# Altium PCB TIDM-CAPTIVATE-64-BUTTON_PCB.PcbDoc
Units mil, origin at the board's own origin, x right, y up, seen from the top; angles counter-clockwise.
Board outline 4300 x 4800 mil, 2 copper layers (Top Layer, Bottom Layer), stack 62 mil thick; 74 components, 17 nets, 1208 pads, 13 vias.
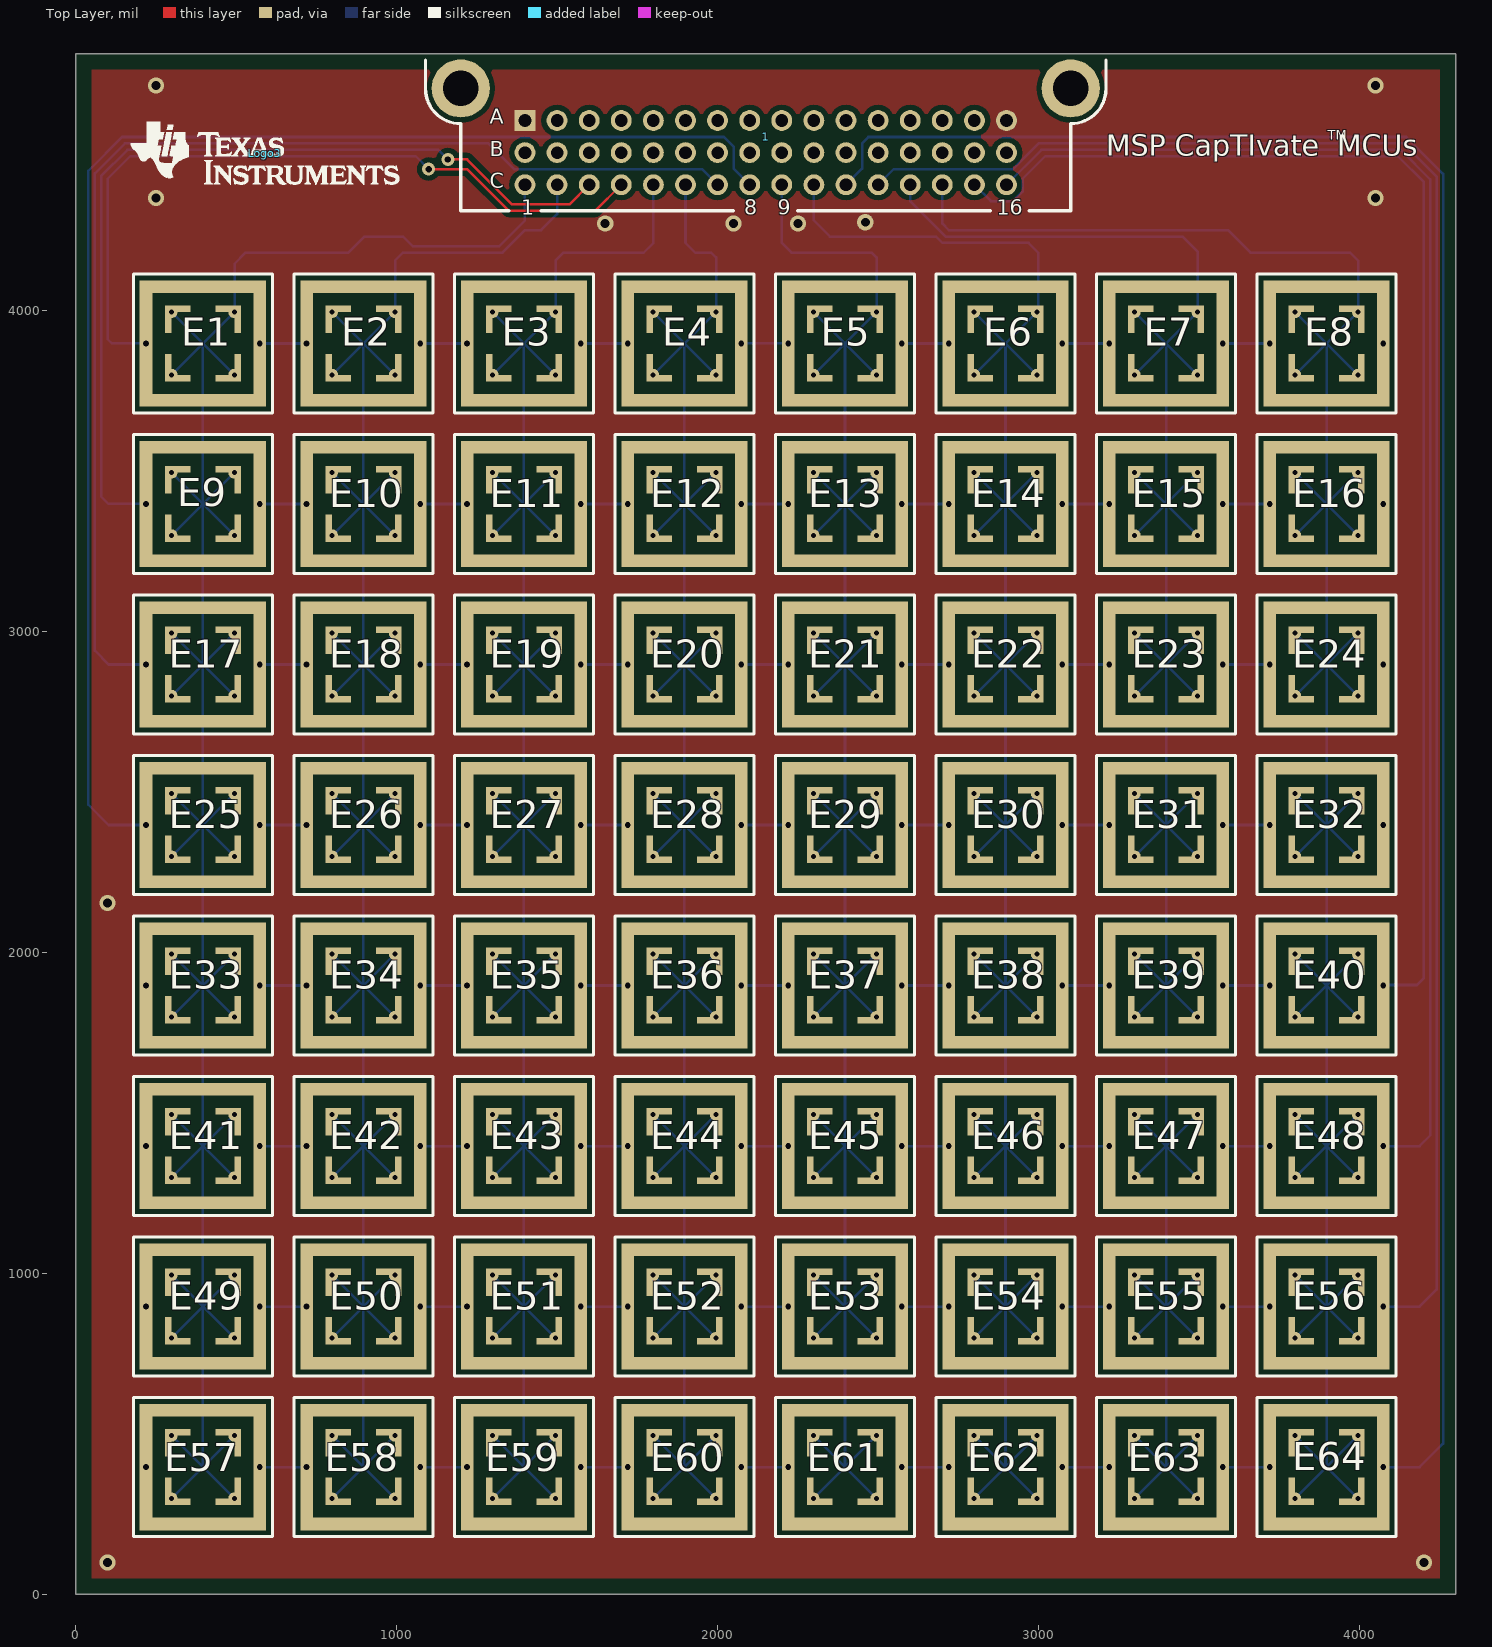
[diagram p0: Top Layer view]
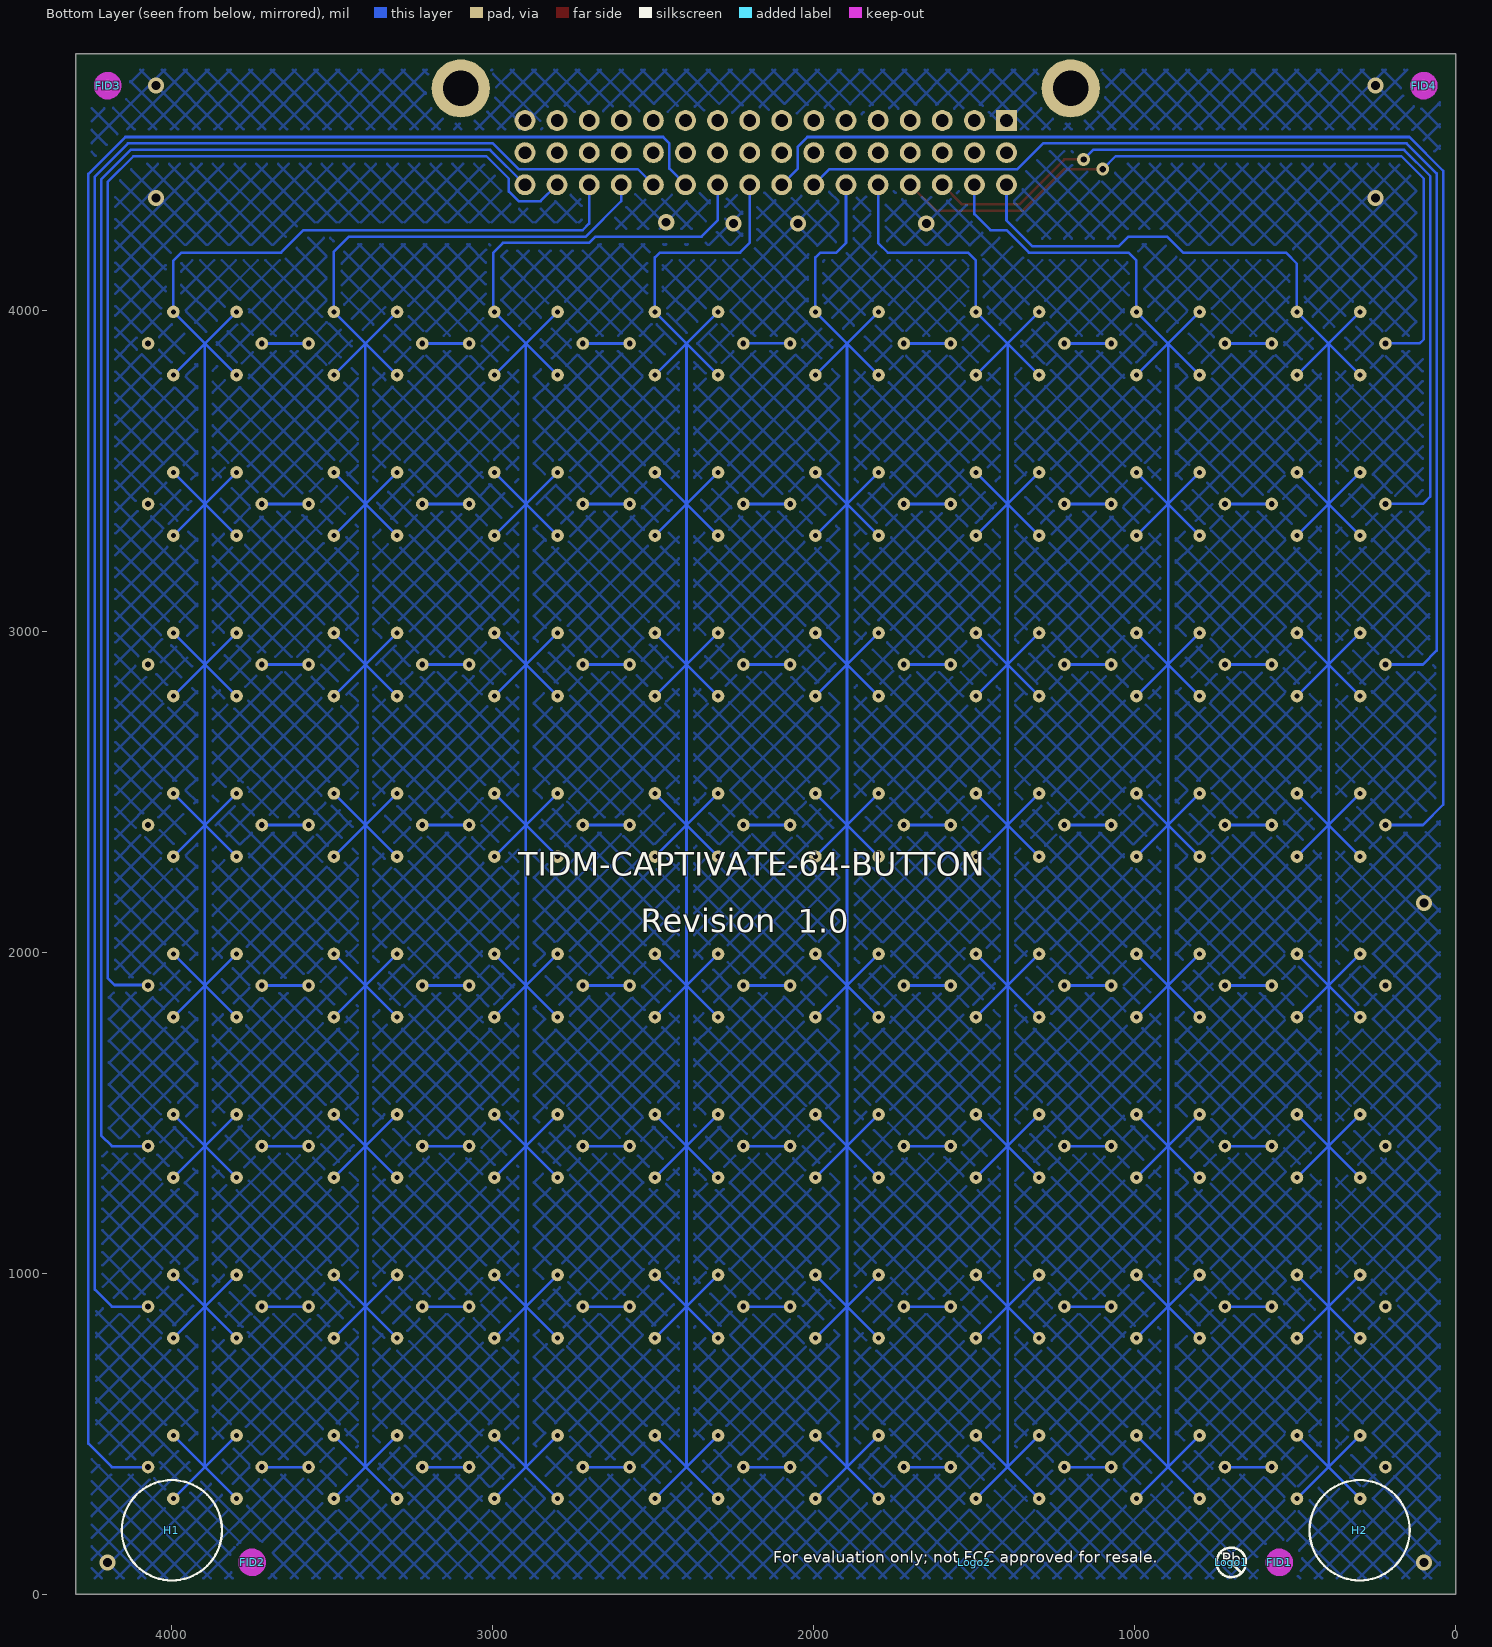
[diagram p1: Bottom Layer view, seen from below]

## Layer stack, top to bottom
Top Solder: solder mask 0.4, Solder Resist, Dk 3.5
Top Layer: signal copper 1.4
Dielectric1: core 59.2, FR-4, Dk 4.8
Bottom Layer: signal copper 1.4
Bottom Solder: solder mask 0.4, Solder Resist, Dk 3.5

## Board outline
0,0 0,4800 4300,4800 4300,0

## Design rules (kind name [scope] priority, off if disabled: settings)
AcuteAngle [All] p1: minimum=3.00000000000000E+0001 checktracksonly=FALSE
AssemblyTestPointUsage [All] p1: valid=2
Clearance Clearance_Keepouts [((IsTrack Or IsArc) And Not InPoly) And IsFree and IsKeepOut vs ((IsTrack Or IsArc) And Not InPoly) And IsFree and IsKeepOut] p1: gap=0
Clearance Clearance_BoardEdge_MountingHoles [OnCopper and InComponentClass('Mounting Holes') vs IsKeepOut] p2: gap=40
Clearance Clearance_BoardEdge_Poly [OnCopper and InPoly vs IsKeepOut] p3: gap=25
Clearance Clearance_BoardEdge [OnCopper and Not InComponentClass('Logo') and not InComponentClass('FiducialMark') and not InRegion(1000,500,4000,800) and Not IsKeepout vs IsKeepOut] p4: gap=75
Clearance Clearance_Poly [InPolygon] p5: gap=16
Clearance [All] p6: gap=6
ComponentClearance ComponentClearance_MountingHoles_FiducialMarks [InComponentClass('Mounting Holes') vs InComponentClass('FiducialMark')] p1: gap=50 collisioncheckmode=3 verticalgap=10 showdistances=FALSE
ComponentClearance ComponentClearance_Shunt [InComponentClass('Header') vs InComponentClass('Shunt')] p2: gap=0 collisioncheckmode=3 verticalgap=0 showdistances=FALSE
ComponentClearance ComponentClearance_Logo [InComponentClass('Logo')] p3: gap=50 collisioncheckmode=3 verticalgap=10 showdistances=FALSE
ComponentClearance ComponentClearance_ScrewToNut [(HasFootprint('NY PMS 440 0025 PH')) vs (HasFootprint('Keystone_1902C'))] p4: gap=5 collisioncheckmode=3 verticalgap=10 showdistances=FALSE
ComponentClearance ComponentClearance_MountingHoles [InComponentClass('Mounting Holes')] p5: gap=250 collisioncheckmode=3 verticalgap=100000 showdistances=FALSE
ComponentClearance ComponentClearance_SmallPassives [HasFootprint('0201*') or HasFootprint('0402*') or HasFootprint('0508') or HasFootprint('0603*') or HasFootprint('0612') or HasFootprint('0805*') or HasFootprint('0815*') or HasFootprint('0830*') or HasFootprint('1206*') or HasFootprint('1210*') or HasFootprint('1808*') or HasFootprint('1812*') or HasFootprint('1825*') or HasFootprint('2010*') or HasFootprint('2220*') or HasFootprint('2225*') or HasFootprint('2512*') or HasFootprint('2728*') or HasFootprint('3518*') vs HasFootprint('0201*') or HasFootprint('0402*') or HasFootprint('0508') or HasFootprint('0603*') or HasFootprint('0612') or HasFootprint('0805*') or HasFootprint('0815*') or HasFootprint('0830*') or HasFootprint('1206*') or HasFootprint('1210*') or HasFootprint('1808*') or HasFootprint('1812*') or HasFootprint('1825*') or HasFootprint('2010*') or HasFootprint('2220*') or HasFootprint('2225*') or HasFootprint('2512*') or HasFootprint('2728*') or HasFootprint('3518*')] p6: gap=20 collisioncheckmode=3 verticalgap=10 showdistances=FALSE
ComponentClearance ComponentClearance_THtoSMT [IsThruComponent vs IsSMTComponent] p7: gap=100 collisioncheckmode=3 verticalgap=30 showdistances=FALSE
ComponentClearance ComponentClearance_THtoTH [IsThruComponent vs IsThruComponent] p8: gap=50 collisioncheckmode=3 verticalgap=30 showdistances=FALSE
ComponentClearance [All] p9: gap=30 collisioncheckmode=3 verticalgap=10 showdistances=FALSE
DiffPairsRouting [All] p1: maxlimit=100 minlimit=10 mostfreqgap=10 toplayer_minwidth=15 toplayer_maxwidth=15 toplayer_prefwidth=15 bottomlayer_minwidth=15 bottomlayer_maxwidth=15 bottomlayer_prefwidth=15 maxuncoupledlength=1000
FabricationTestPointUsage TestPointUsage [All] p1: valid=2 allowmultiple=FALSE
FabricationTestpoint Testpoint [All] p1: side=3 testpointundercomponent=TRUE minsize=40 maxsize=100 preferedsize=60 minholesize=0 maxholesize=40 preferedholesize=32 testpointgrid=1 allowsidetop=TRUE allowsidebottom=TRUE usegrid=TRUE gridtolerance=0.01
FanoutControl Fanout_LCC [IsLCC] p1: bgadir=Out bgaviamode=Centered fanoutstyle=Auto fanoutdirection=Alternating viagrid=1 // Fanout_LCC (Default Rule)
FanoutControl Fanout_BGA [IsBGA] p2: bgadir=Out bgaviamode=Centered fanoutstyle=Auto fanoutdirection=Alternating viagrid=1 // Fanout_BGA (Default Rule)
FanoutControl Fanout_Default [All] p4: bgadir=Out bgaviamode=Centered fanoutstyle=Auto fanoutdirection=Alternating viagrid=1 // Fanout_Default (Default Rule)
FanoutControl Fanout_Small [(CompPinCount < 5)] p5: bgadir=Out bgaviamode=Centered fanoutstyle=Auto fanoutdirection=OutThenIn viagrid=1 // Fanout_Small (Default Rule)
HoleSize [All] p1: absolutevalues=TRUE maxlimit=251 minlimit=8 maxpercent=80.000 minpercent=20.000
MinimumAnnularRing MinimumAnnularRing_ThermalPadVias [IsVia and InAnyComponent] p1: minimumring=5.91
MinimumAnnularRing [All] p2: minimumring=9
MinimumSolderMaskSliver MinimumSolderMaskSliver_Logo [InComponentClass('Logo') vs InComponentClass('Logo')] p1: minsoldermaskwidth=0.7
MinimumSolderMaskSliver [All] p2: minsoldermaskwidth=3.94
PlaneConnect [All] p1: planeconnectstyle=Direct reliefexpansion=10 reliefentries=4 reliefconductorwidth=10 reliefairgap=10
PolygonConnect [All] p1: connectstyle=Direct reliefconductorwidth=10 reliefentries=4 polygonreliefangle="90 Angle" airgapwidth=10
RoutingVias ThermalPadVias [IsVia and InAnyComponent] p1: holewidth=7.87 width=19.68 viastyle="Through Hole" minholewidth=7.87 minwidth=19.68 maxholewidth=12.99 maxwidth=23.62
RoutingVias [All] p2: holewidth=16 width=34 viastyle="Through Hole" minholewidth=7.87 minwidth=26 maxholewidth=40 maxwidth=65
SilkToBoardRegionClearance [Not ((IsComment or IsDesignator) And (Hide <> 'False')) and not InRegion(1000,500,4000,800)] p1:
SilkToSilkClearance SilkToSilkClearance_Pb-FreeLogo [(HasFootprint('Pb-Free_Overlay_Medium') OR HasFootprint('Pb-Free_Overlay_Small')) vs (HasFootprint('Pb-Free_Overlay_Medium') OR HasFootprint('Pb-Free_Overlay_Small'))] p1: silktosilkclearance=0
SilkToSilkClearance [All] p2: silktosilkclearance=5
SilkToSolderMaskClearance "Silk to Solder Mask Opening" [All] p1: minsilkscreentomaskgap=1 clearancetoexposedcopper=FALSE
SolderMaskExpansion [All] p1: expansion=3
UnpouredPolygon [All] p1: allowunpoured=FALSE
Width [All] p1: maxlimit=100 minlimit=6 preferedwidth=10 checkconnectedcopper=TRUE
14 further rules are at their usual default settings.

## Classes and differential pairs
component class Logo: Logo3
component class FiducialMark: FID1 FID2 FID3 FID4
component class TIDM-CAPTIVATE-64-BUTTON_Hardware: FID1 FID2 FID3 FID4 H1 H2 Logo1 Logo2 Logo3 Logo4
component class TIDM-CAPTIVATE-64-BUTTON_Circuit: 1 E1 E2 E3 E4 E5 E6 E7 E8 E9 E10 E11 E12 E13 E14 E15 E16 E17 E18 E19 E20 E21 E22 E23 E24 E25 E26 E27 E28 E29 E30 E31 E32 E33 E34 E35 E36 E37 E38 E39 E40 E41 E42 E43 E44 E45 E46 E47 E48 E49 E50 E51 E52 E53 E54 E55 E56 E57 E58 E59 E60 E61 E62 E63 E64

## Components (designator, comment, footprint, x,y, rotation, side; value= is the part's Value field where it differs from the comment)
1 "CAPTIVATE-CONN-FR2633-PANEL" CAPTIVATE-CONN-48 2150,4800 r0 top
E1 "Btn-Mutual_HighSens" electrode-mutual-highsensitivity-cut-rotated#1 200,3700 r0 top
E2 "Btn-Mutual_HighSens" electrode-mutual-highsensitivity-cut-rotated#1 700,3700 r0 top
E3 "Btn-Mutual_HighSens" electrode-mutual-highsensitivity-cut-rotated#1 1200,3700 r0 top
E4 "Btn-Mutual_HighSens" electrode-mutual-highsensitivity-cut-rotated#1 1700,3700 r0 top
E5 "Btn-Mutual_HighSens" electrode-mutual-highsensitivity-cut-rotated#1 2200,3700 r0 top
E6 "Btn-Mutual_HighSens" electrode-mutual-highsensitivity-cut-rotated#2 2700,3700 r0 top
E7 "Btn-Mutual_HighSens" electrode-mutual-highsensitivity-cut-rotated#1 3200,3700 r0 top
E8 "Btn-Mutual_HighSens" electrode-mutual-highsensitivity-cut-rotated#1 3700,3700 r0 top
E9 "Btn-Mutual_HighSens" electrode-mutual-highsensitivity-cut-rotated#2 200,3200 r0 top
E10 "Btn-Mutual_HighSens" electrode-mutual-highsensitivity-cut-rotated#2 700,3200 r0 top
E11 "Btn-Mutual_HighSens" electrode-mutual-highsensitivity-cut-rotated#2 1200,3200 r0 top
E12 "Btn-Mutual_HighSens" electrode-mutual-highsensitivity-cut-rotated#2 1700,3200 r0 top
E13 "Btn-Mutual_HighSens" electrode-mutual-highsensitivity-cut-rotated#2 2200,3200 r0 top
E14 "Btn-Mutual_HighSens" electrode-mutual-highsensitivity-cut-rotated#2 2700,3200 r0 top
E15 "Btn-Mutual_HighSens" electrode-mutual-highsensitivity-cut-rotated#2 3200,3200 r0 top
E16 "Btn-Mutual_HighSens" electrode-mutual-highsensitivity-cut-rotated#2 3700,3200 r0 top
E17 "Btn-Mutual_HighSens" electrode-mutual-highsensitivity-cut-rotated#2 200,2700 r0 top
E18 "Btn-Mutual_HighSens" electrode-mutual-highsensitivity-cut-rotated#2 700,2700 r0 top
E19 "Btn-Mutual_HighSens" electrode-mutual-highsensitivity-cut-rotated#2 1200,2700 r0 top
E20 "Btn-Mutual_HighSens" electrode-mutual-highsensitivity-cut-rotated#2 1700,2700 r0 top
E21 "Btn-Mutual_HighSens" electrode-mutual-highsensitivity-cut-rotated#2 2200,2700 r0 top
E22 "Btn-Mutual_HighSens" electrode-mutual-highsensitivity-cut-rotated#2 2700,2700 r0 top
E23 "Btn-Mutual_HighSens" electrode-mutual-highsensitivity-cut-rotated#2 3200,2700 r0 top
E24 "Btn-Mutual_HighSens" electrode-mutual-highsensitivity-cut-rotated#2 3700,2700 r0 top
E25 "Btn-Mutual_HighSens" electrode-mutual-highsensitivity-cut-rotated#2 200,2200 r0 top
E26 "Btn-Mutual_HighSens" electrode-mutual-highsensitivity-cut-rotated#2 700,2200 r0 top
E27 "Btn-Mutual_HighSens" electrode-mutual-highsensitivity-cut-rotated#2 1200,2200 r0 top
E28 "Btn-Mutual_HighSens" electrode-mutual-highsensitivity-cut-rotated#2 1700,2200 r0 top
E29 "Btn-Mutual_HighSens" electrode-mutual-highsensitivity-cut-rotated#2 2200,2200 r0 top
E30 "Btn-Mutual_HighSens" electrode-mutual-highsensitivity-cut-rotated#2 2700,2200 r0 top
E31 "Btn-Mutual_HighSens" electrode-mutual-highsensitivity-cut-rotated#2 3200,2200 r0 top
E32 "Btn-Mutual_HighSens" electrode-mutual-highsensitivity-cut-rotated#2 3700,2200 r0 top
E33 "Btn-Mutual_HighSens" electrode-mutual-highsensitivity-cut-rotated#2 200,1700 r0 top
E34 "Btn-Mutual_HighSens" electrode-mutual-highsensitivity-cut-rotated#2 700,1700 r0 top
E35 "Btn-Mutual_HighSens" electrode-mutual-highsensitivity-cut-rotated#2 1200,1700 r0 top
E36 "Btn-Mutual_HighSens" electrode-mutual-highsensitivity-cut-rotated#2 1700,1700 r0 top
E37 "Btn-Mutual_HighSens" electrode-mutual-highsensitivity-cut-rotated#2 2200,1700 r0 top
E38 "Btn-Mutual_HighSens" electrode-mutual-highsensitivity-cut-rotated#2 2700,1700 r0 top
E39 "Btn-Mutual_HighSens" electrode-mutual-highsensitivity-cut-rotated#2 3200,1700 r0 top
E40 "Btn-Mutual_HighSens" electrode-mutual-highsensitivity-cut-rotated#2 3700,1700 r0 top
E41 "Btn-Mutual_HighSens" electrode-mutual-highsensitivity-cut-rotated#2 200,1200 r0 top
E42 "Btn-Mutual_HighSens" electrode-mutual-highsensitivity-cut-rotated#2 700,1200 r0 top
E43 "Btn-Mutual_HighSens" electrode-mutual-highsensitivity-cut-rotated#2 1200,1200 r0 top
E44 "Btn-Mutual_HighSens" electrode-mutual-highsensitivity-cut-rotated#2 1700,1200 r0 top
E45 "Btn-Mutual_HighSens" electrode-mutual-highsensitivity-cut-rotated#2 2200,1200 r0 top
E46 "Btn-Mutual_HighSens" electrode-mutual-highsensitivity-cut-rotated#2 2700,1200 r0 top
E47 "Btn-Mutual_HighSens" electrode-mutual-highsensitivity-cut-rotated#2 3200,1200 r0 top
E48 "Btn-Mutual_HighSens" electrode-mutual-highsensitivity-cut-rotated#2 3700,1200 r0 top
E49 "Btn-Mutual_HighSens" electrode-mutual-highsensitivity-cut-rotated#2 200,700 r0 top
E50 "Btn-Mutual_HighSens" electrode-mutual-highsensitivity-cut-rotated#2 700,700 r0 top
E51 "Btn-Mutual_HighSens" electrode-mutual-highsensitivity-cut-rotated#2 1200,700 r0 top
E52 "Btn-Mutual_HighSens" electrode-mutual-highsensitivity-cut-rotated#2 1700,700 r0 top
E53 "Btn-Mutual_HighSens" electrode-mutual-highsensitivity-cut-rotated#2 2200,700 r0 top
E54 "Btn-Mutual_HighSens" electrode-mutual-highsensitivity-cut-rotated#2 2700,700 r0 top
E55 "Btn-Mutual_HighSens" electrode-mutual-highsensitivity-cut-rotated#2 3200,700 r0 top
E56 "Btn-Mutual_HighSens" electrode-mutual-highsensitivity-cut-rotated#2 3700,700 r0 top
E57 "Btn-Mutual_HighSens" electrode-mutual-highsensitivity-cut-rotated#2 200,200 r0 top
E58 "Btn-Mutual_HighSens" electrode-mutual-highsensitivity-cut-rotated#2 700,200 r0 top
E59 "Btn-Mutual_HighSens" electrode-mutual-highsensitivity-cut-rotated#2 1200,200 r0 top
E60 "Btn-Mutual_HighSens" electrode-mutual-highsensitivity-cut-rotated#2 1700,200 r0 top
E61 "Btn-Mutual_HighSens" electrode-mutual-highsensitivity-cut-rotated#2 2200,200 r0 top
E62 "Btn-Mutual_HighSens" electrode-mutual-highsensitivity-cut-rotated#2 2700,200 r0 top
E63 "Btn-Mutual_HighSens" electrode-mutual-highsensitivity-cut-rotated#2 3200,200 r0 top
E64 "Btn-Mutual_HighSens" electrode-mutual-highsensitivity-cut-rotated#2 3700,200 r0 top
FID1 "Fiducial" Fiducial10-20 550,100 r180 bottom
FID2 "Fiducial" Fiducial10-20 3750,100 r180 bottom
FID3 "Fiducial" Fiducial10-20 4200,4700 r180 bottom
FID4 "Fiducial" Fiducial10-20 100,4700 r180 bottom
H1 "SJ61A1" Bumpon_SJ61A1 4000,200 r180 bottom
H2 "SJ61A1" Bumpon_SJ61A1 300,200 r180 bottom
Logo1 "Pb-Free Symbol" Pb-Free_Overlay_Small 700,100 r180 bottom
Logo2 "FCC disclaimer" FCC_disclaimer 1500,100 r180 bottom
Logo3 "Texas Instruments" TI_Stacked_Overlay_Small 590,4490 r0 top

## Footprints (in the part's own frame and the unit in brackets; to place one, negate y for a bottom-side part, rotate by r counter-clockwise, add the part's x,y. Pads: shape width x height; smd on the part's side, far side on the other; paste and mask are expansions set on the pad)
Bumpon_SJ61A1 [mil] "3M Cylindrical Bumpon black"
  round 1 on Mech4: 0(0,0)
  silkscreen extent -156,-156 156,156, body extent -156,-155 156,156, height 201
CAPTIVATE-CONN-48 [mm] "Connector, 3x16, 100mil, TH, RA"
  rect 1.65x1.65 hole 1: A1(-19.05,-5.3)
  round 1.65 hole 1: A2(-16.51,-5.3) A3(-13.97,-5.3) A4(-11.43,-5.3) A5(-8.89,-5.3) A6(-6.35,-5.3) A7(-3.81,-5.3) A8(-1.27,-5.3) A9(1.27,-5.3) A10(3.81,-5.3) A11(6.35,-5.3) A12(8.89,-5.3) A13(11.43,-5.3) A14(13.97,-5.3) A15(16.51,-5.3) A16(19.05,-5.3) B1(-19.05,-7.84) B2(-16.51,-7.84) B3(-13.97,-7.84) B4(-11.43,-7.84) B5(-8.89,-7.84) B6(-6.35,-7.84) B7(-3.81,-7.84) B8(-1.27,-7.84) B9(1.27,-7.84) B10(3.81,-7.84) B11(6.35,-7.84) B12(8.89,-7.84) B13(11.43,-7.84) B14(13.97,-7.84) B15(16.51,-7.84) B16(19.05,-7.84) C1(-19.05,-10.38) C2(-16.51,-10.38) C3(-13.97,-10.38) C4(-11.43,-10.38) C5(-8.89,-10.38) C6(-6.35,-10.38) C7(-3.81,-10.38) C8(-1.27,-10.38) C9(1.27,-10.38) C10(3.81,-10.38) C11(6.35,-10.38) C12(8.89,-10.38) C13(11.43,-10.38) C14(13.97,-10.38) C15(16.51,-10.38) C16(19.05,-10.38)
  round 4.6 hole 2.8: H1(-24.13,-2.76) H2(24.13,-2.76)
  silkscreen extent -26.92,-12.45 26.92,-0.51, body extent -27.05,-5.46 27.05,6.98, height 6.6
electrode-mutual-highsensitivity-cut-rotated#1 [mm] "Mutual Capacitance Sensing Electrode with High Sensitivity and Cut Rx Square (Rotated)"
  rect 0.5x1.667 smd paste+0: RX(2.25,3.333) RX(2.25,6.667) RX(7.75,3.333) RX(7.75,6.667)
  round 1 hole 0.4: RX(2.5,2.5) RX(2.5,7.5) RX(7.5,2.5) RX(7.5,7.5)
  rect 2x0.5 smd paste+0: RX(3,2.25) RX(3,7.75) RX(7,2.25) RX(7,7.75)
  rect 1x10 smd paste+0: TX(0.5,5) TX(9.5,5)
  round 1 hole 0.45: TX(0.5,5) TX(9.5,5)
  rect 10x1 smd paste+0: TX(5,0.5) TX(5,9.5)
  Bottom Layer lines w0.2: 2.5,2.5 5,5 ; 2.5,7.5 5,5 ; 7.5,2.5 5,5 ; 7.5,7.5 5,5
  silkscreen extent -0.5,-0.5 10.5,10.5
electrode-mutual-highsensitivity-cut-rotated#2 [mm] "Mutual Capacitance Sensing Electrode with High Sensitivity and Cut Rx Square (Rotated)"
  rect 0.5x1.667 smd paste+0: RX(2.25,3.333) RX(2.25,6.667) RX(7.75,3.333) RX(7.75,6.667)
  round 1 hole 0.4: RX(2.5,2.5) RX(2.5,7.5) RX(7.5,2.5) RX(7.5,7.5)
  rect 2x0.5 smd paste+0: RX(3,2.25) RX(3,7.75) RX(7,2.25) RX(7,7.75)
  rect 1x10 smd paste+0: TX(0.5,5) TX(9.5,5)
  round 1 hole 0.45: TX(0.5,5) TX(9.5,5)
  rect 10x1 smd paste+0: TX(5,0.5) TX(5,9.5)
  Bottom Layer lines w0.2: 2.5,2.5 7.5,7.5 ; 2.5,7.5 7.5,2.5
  silkscreen extent -0.5,-0.5 10.5,10.5
FCC_disclaimer [mil]
Fiducial10-20 [mm]
  round 1 smd mask+0.5: 1(0,0)
  Top Layer keep-out circle w1.178: c0,0 r0.5
Pb-Free_Overlay_Small [mil]
  silkscreen extent -46,-46 46,46
TI_Stacked_Overlay_Small [mil]
  silkscreen extent -418,-98 418,98

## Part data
1: library part CAPTIVATE-CONN-MSP-EXP430FR2633-PANEL, "CapTIvate Panel-Side Connector, 3x16, 100mil, TH, RA, M, MSP-EXP430FR2633"
E1 E2 E3 E4 E5 E6 E7 E8 E9 E10 E11 E12 E13 E14 E15 E16 E17 E18 E19 E20 E21 E22 E23 E24 E25 E26 E27 E28 E29 E30 E31 E32 E33 E34 E35 E36 E37 E38 E39 E40 E41 E42 E43 E44 E45 E46 E47 E48 E49 E50 E51 E52 E53 E54 E55 E56 E57 E58 E59 E60 E61 E62 E63 E64: library part btn-mutual-highsens, "Capacitive Button, Mutual, 2-layer, 10mm, High Sensitivity"
FID1 FID2 FID3 FID4: "Fiducial mark.  There is nothing to buy or mount."
H1 H2: "Bumpon, Cylindrical, 0.312 X 0.200, Black"
Logo1: library part Pb-Free
Logo2: library part FCC_disclaimer, "FCC_disclaimer"
Logo3: library part TI_Logo, "Texas Instrument Corporate Signature"

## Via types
v1: diameter 50, hole 28, Top Layer to Bottom Layer, 11 vias
v2: diameter 40, hole 20, Top Layer to Bottom Layer, 2 vias

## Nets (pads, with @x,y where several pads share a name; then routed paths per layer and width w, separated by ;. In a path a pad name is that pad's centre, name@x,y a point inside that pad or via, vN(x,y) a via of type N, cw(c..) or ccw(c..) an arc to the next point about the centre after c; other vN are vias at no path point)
GND: 1.A1 1.A16
  other v1: 100,100 4200.18,99.82 100,2154.23 1650,4269.87 2050,4270 2250,4270 2460,4274.46 250,4350 4050,4350 250,4700 4050,4700
RX0: 1.C1 E1.RX E9.RX E17.RX E25.RX E33.RX E41.RX E49.RX E57.RX | length 4746.7
  Bottom Layer w7.87: 396.85,396.85 396.85,3896.85 ; E1.RX@495.28,3995.28 495.28,4145.28 530,4180 850,4180 900,4230 1020,4230 1050,4200 1320,4200 1400,4280 1.C1
RX1: 1.C2 E2.RX E10.RX E18.RX E26.RX E34.RX E42.RX E50.RX E58.RX | length 4316
  Bottom Layer w7.87: 896.85,396.85 896.85,3896.85 ; E2.RX@995.28,3995.28 995.28,4155.28 1020,4180 1330,4180 1400,4250 1450,4250 1500,4300 1.C2
RX2: 1.C5 E3.RX E11.RX E19.RX E27.RX E35.RX E43.RX E51.RX E59.RX | length 4168.7
  Bottom Layer w7.87: 1396.85,396.85 1396.85,3896.85 ; E3.RX@1495.28,3995.28 1495.28,4155.28 1520,4180 1770,4180 1800,4210 1.C5
RX3: 1.C6 E4.RX E12.RX E20.RX E28.RX E36.RX E44.RX E52.RX E60.RX | length 3964.8
  Bottom Layer w7.87: 1896.85,396.85 1896.85,3896.85 ; 1.C6 1900,4210 1930,4180 1980,4180 1995.28,4164.72 E4.RX@1995.28,3995.28
RX4: 1.C9 E5.RX E13.RX E21.RX E29.RX E37.RX E45.RX E53.RX E61.RX | length 4164.8
  Bottom Layer w7.87: 1.C9 2200,4210 2230,4180 2480,4180 2495.28,4164.72 E5.RX@2495.28,3995.28 ; 2396.85,396.85 2396.85,3896.85
RX5: 1.C10 E6.RX E14.RX E22.RX E30.RX E38.RX E46.RX E54.RX E62.RX | length 4532.8
  Bottom Layer w7.87: 1.C10 2300,4280 2350,4230 2680,4230 2700,4210 2968.5,4210 2998.5,4180 E6.RX@2998.5,3998.5 ; 2896.85,396.85 2896.85,3896.85
RX6: 1.C13 E7.RX E15.RX E23.RX E31.RX E39.RX E47.RX E55.RX E63.RX | length 4699.5
  Bottom Layer w7.87: 1.C13 2600,4340 2710,4230 3448.5,4230 3495.28,4183.23 E7.RX@3495.28,3995.28 ; 3396.85,396.85 3396.85,3896.85
RX7: 1.C14 E8.RX E16.RX E24.RX E32.RX E40.RX E48.RX E56.RX E64.RX | length 5123.8
  Bottom Layer w7.87: 1.C14 2700,4270 2720,4250 3590,4250 3660,4180 3970,4180 3995.28,4154.72 E8.RX@3995.28,3995.28 ; 3896.85,396.85 3896.85,3896.85
TX0: 1.C4 E1.TX E2.TX E3.TX E4.TX E5.TX E6.TX E7.TX E8.TX | length 3377.9
  Top Layer w7.87: v2(1100,4440) 1220,4440 1350,4310 1618.66,4310 1.C4
  Bottom Layer w7.87: E1.TX@219.68,3896.85 113.15,3896.85 100,3910 100,4410 170,4480 1060,4480 v2(1100,4440) ; E4.TX@2074.02,3896.85 E5.TX@2219.68,3896.85
  Bottom Layer w8: E1.TX@574.02,3896.85 E2.TX@719.68,3896.85 ; E2.TX@1074.02,3896.85 E3.TX@1219.68,3896.85 ; E3.TX@1574.02,3896.85 E4.TX@1719.68,3896.85 ; E5.TX@2574.02,3896.85 E6.TX@2719.68,3896.85 ; E6.TX@3074.02,3896.85 E7.TX@3219.68,3896.85 ; E7.TX@3574.02,3896.85 E8.TX@3719.69,3896.85
TX1: 1.C3 E9.TX E10.TX E11.TX E12.TX E13.TX E14.TX E15.TX E16.TX | length 3816.9
  Top Layer w7.87: v2(1160,4470) 1220,4470 1360,4330 1538.66,4330 1.C3
  Bottom Layer w7.87: E9.TX@219.68,3396.85 103.15,3396.85 80,3420 80,4418.28 161.72,4500 1130,4500 v2(1160,4470)
  Bottom Layer w8: E9.TX@574.02,3396.85 E10.TX@719.68,3396.85 ; E10.TX@1074.02,3396.85 E11.TX@1219.68,3396.85 ; E11.TX@1574.02,3396.85 E12.TX@1719.68,3396.85 ; E12.TX@2074.02,3396.85 E13.TX@2219.68,3396.85 ; E13.TX@2574.02,3396.85 E14.TX@2719.68,3396.85 ; E14.TX@3074.02,3396.85 E15.TX@3219.68,3396.85 ; E15.TX@3574.02,3396.85 E16.TX@3719.69,3396.85
TX2: 1.C7 E17.TX E18.TX E19.TX E20.TX E21.TX E22.TX E23.TX E24.TX | length 4715.8
  Bottom Layer w7.87: E17.TX@219.68,2896.85 103.15,2896.85 60,2940 60,4426.57 153.43,4520 1286.21,4520 1366.21,4440 1951.34,4440 1.C7
  Bottom Layer w8: E17.TX@574.02,2896.85 E18.TX@719.68,2896.85 ; E18.TX@1074.02,2896.85 E19.TX@1219.68,2896.85 ; E19.TX@1574.02,2896.85 E20.TX@1719.68,2896.85 ; E20.TX@2074.02,2896.85 E21.TX@2219.68,2896.85 ; E21.TX@2574.02,2896.85 E22.TX@2719.68,2896.85 ; E22.TX@3074.02,2896.85 E23.TX@3219.68,2896.85 ; E23.TX@3574.02,2896.85 E24.TX@3719.69,2896.85
TX3: 1.C8 E25.TX E26.TX E27.TX E28.TX E29.TX E30.TX E31.TX E32.TX | length 5405.7
  Bottom Layer w7.87: E25.TX@219.68,2396.85 103.15,2396.85 40,2460 40,4434.85 145.15,4540 2020,4540 2050,4510 2050,4441.34 1.C8 ; E29.TX@2574.02,2396.85 E30.TX@2719.68,2396.85
  Bottom Layer w8: E25.TX@574.02,2396.85 E26.TX@719.68,2396.85 ; E26.TX@1074.02,2396.85 E27.TX@1219.68,2396.85 ; E27.TX@1574.02,2396.85 E28.TX@1719.68,2396.85 ; E28.TX@2074.02,2396.85 E29.TX@2219.68,2396.85 ; E30.TX@3074.02,2396.85 E31.TX@3219.68,2396.85 ; E31.TX@3574.02,2396.85 E32.TX@3719.69,2396.85
TX4: 1.C15 E33.TX E34.TX E35.TX E36.TX E37.TX E38.TX E39.TX E40.TX | length 5168.7
  Bottom Layer w7.87: 1.C15 2851.34,4340 2920,4340 2950,4370 2950,4410 3020,4480 4120,4480 4200,4400 4200,1920 4178.5,1898.5 4140,1898.5 E40.TX@4075.67,1898.5
  Bottom Layer w8: E33.TX@574.02,1896.85 E34.TX@719.68,1896.85 ; E34.TX@1074.02,1896.85 E35.TX@1219.68,1896.85 ; E35.TX@1574.02,1896.85 E36.TX@1719.68,1896.85 ; E36.TX@2074.02,1896.85 E37.TX@2219.68,1896.85 ; E37.TX@2574.02,1896.85 E38.TX@2719.68,1896.85 ; E38.TX@3074.02,1896.85 E39.TX@3219.68,1896.85 ; E39.TX@3574.02,1896.85 E40.TX@3719.69,1896.85
TX5: 1.C16 E41.TX E42.TX E43.TX E44.TX E45.TX E46.TX E47.TX E48.TX | length 5560.7
  Bottom Layer w7.87: 1.C16 3008.66,4500 4128.28,4500 4220,4408.28 4220,1430 4186.85,1396.85 E48.TX@4074.02,1396.85
  Bottom Layer w8: E41.TX@574.02,1396.85 E42.TX@719.68,1396.85 ; E42.TX@1074.02,1396.85 E43.TX@1219.68,1396.85 ; E43.TX@1574.02,1396.85 E44.TX@1719.68,1396.85 ; E44.TX@2074.02,1396.85 E45.TX@2219.68,1396.85 ; E45.TX@2574.02,1396.85 E46.TX@2719.68,1396.85 ; E46.TX@3074.02,1396.85 E47.TX@3219.68,1396.85 ; E47.TX@3574.02,1396.85 E48.TX@3719.69,1396.85
TX6: 1.C12 E49.TX E50.TX E51.TX E52.TX E53.TX E54.TX E55.TX E56.TX | length 6510.4
  Bottom Layer w7.87: 1.C12 2548.66,4440 2920,4440 3000,4520 4136.57,4520 4240,4416.57 4240,950 4186.85,896.85 E56.TX@4074.02,896.85
  Bottom Layer w8: E49.TX@574.02,896.85 E50.TX@719.68,896.85 ; E50.TX@1074.02,896.85 E51.TX@1219.68,896.85 ; E51.TX@1574.02,896.85 E52.TX@1719.68,896.85 ; E52.TX@2074.02,896.85 E53.TX@2219.68,896.85 ; E53.TX@2574.02,896.85 E54.TX@2719.68,896.85 ; E54.TX@3074.02,896.85 E55.TX@3219.68,896.85 ; E55.TX@3574.02,896.85 E56.TX@3719.69,896.85
TX7: 1.C11 E57.TX E58.TX E59.TX E60.TX E61.TX E62.TX E63.TX E64.TX | length 7206.2
  Bottom Layer w7.87: 1.C11 2450,4441.34 2450,4520 2470,4540 4144.85,4540 4260,4424.85 4260,470 4186.85,396.85 E64.TX@4074.02,396.85
  Bottom Layer w8: E57.TX@574.02,396.85 E58.TX@719.68,396.85 ; E58.TX@1074.02,396.85 E59.TX@1219.68,396.85 ; E59.TX@1574.02,396.85 E60.TX@1719.68,396.85 ; E60.TX@2074.02,396.85 E61.TX@2219.68,396.85 ; E61.TX@2574.02,396.85 E62.TX@2719.68,396.85 ; E62.TX@3074.02,396.85 E63.TX@3219.68,396.85 ; E63.TX@3574.02,396.85 E64.TX@3719.69,396.85
pads on no net: 1.A2 1.A3 1.A4 1.A5 1.A6 1.A7 1.A8 1.A9 1.A10 1.A11 1.A12 1.A13 1.A14 1.A15 1.B1 1.B2 1.B3 1.B4 1.B5 1.B6 1.B7 1.B8 1.B9 1.B10 1.B11 1.B12 1.B13 1.B14 1.B15 1.B16 1.H1 1.H2 FID1.1 FID2.1 FID3.1 FID4.1 H1.0 H2.0

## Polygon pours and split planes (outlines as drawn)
GND on Top Layer "Top Layer-No Net" (solid, remove dead copper, pour order 2): 50,4750 4250,4750 4250,50 50,50 50,4750
GND on Bottom Layer "Bottom Layer-No Net" (hatched 45Degree grid 48 track 8, remove dead copper, pour order 4): 50,4750 4250,4750 4250,50 50,50 50,4750

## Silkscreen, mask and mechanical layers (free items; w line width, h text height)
Top Overlay:
  text "TM" at 3900,4520 h50
  text "MSP CapTIvate  MCUs" at 3210,4460 h110
Bottom Overlay:
  text "TIDM-CAPTIVATE-64-BUTTON" at 2920.79,2214.55 h125
  text "1.0" at 2050,2037.05 h125
  text "Revision" at 2540,2037.41 h125
M1 Board Outline:
  the board outline again, w7.87
M2 Board Dimensions:
  rectangle: 125,-400 500,-275
  rectangle: 0,-275 125,-150
  lines w7: 0,-275 1000,-275 ; 125,-400 125,-150 ; 250,-400 250,-150 ; 500,-400 500,-150 ; 750,-400 750,-150 ; 0,-400 0,-150 1000,-150 1000,-400 0,-400
M5 Assembly Top:
  lines w10: -292,-523.5 -292,-1133.5 3713,-1133.5 ; -291.5,-523.5 -291.5,-1133.5 1284,-1133.5
M6 Assembly Bottom:
  lines w10: -292.5,-524 -292.5,-1134 2304.5,-1134
M9 Title Sheet:
  lines w10: -491.5,1041.5 -291.5,1041.5 ; -491.5,3416.5 -291.5,3416.5 ; -491.5,5791.5 -291.5,5791.5 ; 2008.5,-1333.5 2008.5,-1133.5 ; 2008.5,7966.5 2008.5,8166.5 ; 4508.5,-1333.5 4508.5,-1133.5 ; 4508.5,7966.5 4508.5,8166.5 ; 7008.5,-1333.5 7008.5,-1133.5 ; 7008.5,7966.5 7008.5,8166.5 ; 9508.5,-1333.5 9508.5,-1133.5 ; 9508.5,7966.5 9508.5,8166.5 ; 11303.5,-1133.5 11303.5,-523.5 ; 11303.5,-823.5 14303.5,-823.5 ; 11303.5,-223.5 14303.5,-223.5 ; 11303.5,76.5 11303.5,-523.5 ; 12008.5,-1333.5 12008.5,-1133.5 ; 12008.5,7966.5 12008.5,8166.5 ; 12808.5,-1123.5 12808.5,-523.5 ; 14303.5,-523.5 11303.5,-523.5 ; 14308.5,66.5 14308.5,-1133.5 ; 14308.5,3416.5 14508.5,3416.5 ; 14308.5,5791.5 14508.5,5791.5 ; 14308.5,-1133.5 -291.5,-1133.5 -291.5,7966.5 14308.5,7966.5 14308.5,-1133.5 ; -491.5,-1333.5 14508.5,-1333.5 14508.5,8166.5 -491.5,8166.5 -491.5,-1333.5
  text "1" at 739.84,8036.5 h70
  text "2" at 3235.5,8036.5 h70
  text "3" at 5724.84,8036.5 h70
  text "4" at 8231.51,8036.5 h70
  text "5" at 10730.5,8036.5 h70
  text "6" at 13235.5,8036.5 h70
  text "A" at -416.5,6893.5 h70
  text "A" at 14383.5,6893.5 h70
  text "B" at -416.5,4513.5 h70
  text "B" at 14383.5,4513.5 h70
  text "C" at -416.5,2138.5 h70
  text "D" at -416.5,-231.5 h70
  text "D" at 14383.5,-231.5 h70
  text "FILE NAME:" at 11343.5,-323.5 h45
  text ".PCB_File_Name_No_Path" at 11393.5,-443.5 h70
  text "ENGINEER:" at 11343.5,-613.5 h45
  text "LAYOUT BY:" at 12848.5,-613.5 h45
  text ".PRJ_Engineer" at 11393.5,-768.49 h70
  text ".PCB_Layout" at 12899,-768.49 h70
  text "ALTIUM DESIGNER VERSION:" at 12848.5,-923.5 h45
  text ".print_Scale" at 11393.5,-1056.83 h70
  text ".Application_BuildNumber" at 12899,-1056.83 h70
  text "1" at 739.84,-1263.5 h70
  text "2" at 3235.5,-1263.5 h70
  text "3" at 5724.84,-1263.5 h70
  text "4" at 8231.51,-1263.5 h70
  text "5" at 10730.5,-1263.5 h70
  text "6" at 13235.5,-1263.5 h70
M10 Fab Notes:
  lines w8: 12157.46,2508.64 12157.46,2646.64 12295.46,2646.64 12295.46,2508.64 ; 12750,5442 12955.39,5442 ; 12750,5574.99 12955.39,5574.99 ; 12750,5705.99 12955.39,5705.99 ; 13004.46,3891.64 13713.46,3891.64 ; 13004.46,4204.64 13713.46,4204.64 ; 13123,5060 13283.39,5060 ; 13388.46,3052.64 14231.46,3052.64 ; 13520,2510 13520,2648 13658,2648 13658,2510 ; 13556.46,4686 14265.46,4686 ; 13606.46,4530 14265,4530 ; 13626.46,2705.64 14269.46,2705.64 ; 13706.46,3475.64 14174.46,3475.64 ; 13956,5060 14116.39,5060 ; 14126.46,2666.64 14264.46,2666.64 ; 11557.46,4685.64 11695.46,4685.64 11695.46,4823.64 11557.46,4823.64 11557.46,4685.64 ; 11895.46,4518.64 12033.46,4518.64 12033.46,4656.64 11895.46,4656.64 11895.46,4518.64 ; 12006.46,2705.64 12144.46,2705.64 12144.46,2843.64 12006.46,2843.64 12006.46,2705.64 ; 12006.46,3633.64 12144.46,3633.64 12144.46,3771.64 12006.46,3771.64 12006.46,3633.64 ; 12116.46,4685.64 12254.46,4685.64 12254.46,4823.64 12116.46,4823.64 12116.46,4685.64 ; 12197.46,3891.64 12197.46,4029.64 12335.46,4029.64 12335.46,3891.64 12197.46,3891.64 ; 12197.46,4047.64 12335.46,4047.64 12335.46,4185.64 12197.46,4185.64 12197.46,4047.64 ; 12197.46,4204.64 12335.46,4204.64 12335.46,4342.64 12197.46,4342.64 12197.46,4204.64 ; 12197.46,4360.64 12335.46,4360.64 12335.46,4498.64 12197.46,4498.64 12197.46,4360.64 ; 12386.46,3031.64 12524.46,3031.64 12524.46,3169.64 12386.46,3169.64 12386.46,3031.64 ; 12387.46,3198.64 12525.46,3198.64 12525.46,3336.64 12387.46,3336.64 12387.46,3198.64 ; 12597.46,2705.64 12735.46,2705.64 12735.46,2843.64 12597.46,2843.64 12597.46,2705.64 ; 12708.46,3475.64 12846.46,3475.64 12846.46,3613.64 12708.46,3613.64 12708.46,3475.64 ; 12897.46,3031.64 13035.46,3031.64 13035.46,3169.64 12897.46,3169.64 12897.46,3031.64 ; 12897.46,3198.64 13035.46,3198.64 13035.46,3336.64 12897.46,3336.64 12897.46,3198.64 ; 12907.46,3633.64 13045.46,3633.64 13045.46,3771.64 12907.46,3771.64 12907.46,3633.64 ; 13005.46,4686 13005.46,4824 13143.46,4824 13143.46,4686 13005.46,4686 ; 13109.46,2705.64 13109.46,2843.64 13247.46,2843.64 13247.46,2705.64 13109.46,2705.64 ; 13182.46,4518.64 13320.46,4518.64 13320.46,4656.64 13182.46,4656.64 13182.46,4518.64 ; 13230.46,3475.64 13368.46,3475.64 13368.46,3613.64 13230.46,3613.64 13230.46,3475.64
  lines w20: 11303,876 11303,6009 14294,6009 14294,876 ; 11303,5029.45 14294.46,5029.45 ; 11303,5871 14294,5871
  text "DESIGN INFORMATION" at 12381.02,5910 h60
  text "MIN. TRACK WIDTH:" at 11736.46,5730 h60
  text "8" at 12832.7,5730 h60
  text "MIL" at 12987.46,5730 h60
  text "MIN. CLEARANCE:" at 11736.46,5598 h60
  text "0.2" at 12772.7,5598 h60
  text "mm" at 12987.46,5598 h60
  text "MIN. VIA PAD SIZE:" at 11736.46,5466 h60
  text "24" at 12802.71,5466 h60
  text "MIL" at 12987.46,5466 h60
  text "0.05mm (2MIL)" at 12431.46,5324.29 h60
  text "MINIMUM ANNULAR RING" at 11407.23,5320 h60
  text "EXTERNAL" at 13139.46,5320 h60
  text "PER" at 11607.23,5202 h60
  text "IPC-D-275 CLASS 2 LEVEL C" at 11827.23,5202 h60
  text "MIL, HOLES" at 13315.46,5089.71 h60
  text "+/-" at 12923,5089 h60
  text "+/-" at 13777,5089 h60
  text "REGISTRATION TOLERANCES:" at 11407.23,5084 h60
  text "METAL" at 12607,5084 h60
  text "5" at 13183.2,5084 h60
  text "3" at 14016.2,5084 h60
  text "MIL" at 14132.46,5084 h60
  text "MATERIAL:" at 11332.46,4874.54 h60
  text "FR-4 High Tg" at 12318.9,4734.21 h60
  text "FR-408" at 11753.46,4725.64 h60
  text "X" at 12165.46,4725.64 h60
  text "OTHER" at 13241.46,4725.64 h60
  text "62 MIL (1.6mm) +/-10%" at 12073.56,4562.92 h60
  text "THICKNESS:" at 11407.23,4558.64 h60
  text "X" at 11945.4,4558.64 h60
  text "OTHER" at 13358.46,4558.64 h60
  text "TOLERANCE:" at 11407.23,4400.64 h60
  text "X" at 12246.53,4400.64 h60
  text "ANSI IPC-6012 TYPE 3 CLASS 2" at 12433.48,4400.64 h60
  text "OTHER +/-" at 12433.46,4244.64 h60
  text "BOW & TWIST:" at 11407.23,4087.64 h60
  text "X" at 12246.53,4087.64 h60
  text "ANSI IPC-6012 TYPE 3 CLASS 2" at 12433.48,4087.64 h60
  text "OTHER +/-" at 12433.46,3929.13 h60
  text "DRILLING:" at 11332.46,3790.64 h60
  text "REFERENCE:" at 11407.23,3673.64 h60
  text "X" at 12055.46,3673.64 h60
  text "AS SHOWN" at 12242.46,3673.64 h60
  text "X" at 12956.46,3673.64 h60
  text "NC_DRILL FILES" at 13093.46,3673.64 h60
  text "PTH MIN COPPER THICKNESS:" at 11407.23,3515.64 h60
  text "X" at 12757.46,3515.64 h60
  text "1MIL" at 12894.46,3515.64 h60
  text "OTHER" at 13391.46,3515.64 h60
  text "BOARD FINISH:" at 11332.46,3356.64 h60
  text "SILKSCREEN:" at 11487.68,3238.64 h60
  text "X" at 12436.46,3238.64 h60
  text "TOP" at 12562.46,3238.64 h60
  text "X" at 12946.46,3238.64 h60
  text "BOTTOM" at 13073.46,3238.64 h60
  text "SILKSCREEN COLOR:" at 11487.68,3071.64 h60
  text "X" at 12435.42,3071.64 h60
  text "WHITE" at 12562.46,3071.64 h60
  text "OTHER" at 13073.46,3071.64 h60
  text "SOLDER RESIST COLOR:" at 11487.68,2901.64 h60
  text "X" at 12055.42,2742.44 h60
  text "GREEN" at 12182.46,2742.44 h60
  text "BLUE" at 12773.46,2742.44 h60
  text "OTHER" at 13311.46,2742.44 h60
  text "IMMERSION GOLD (ENIG)" at 12393.46,2553.92 h60
  text "ENEPIG" at 13731,2550.64 h60
  text "SURFACE FINISH:" at 11332.46,2549.64 h60
  text "X" at 12206.51,2549.64 h60
M11 Gerber Information:
  lines w10: -292,-523.5 -292,-1133.5 3713,-1133.5 ; -291.5,-523.5 -291.5,-1133.5 1284,-1133.5
M12 Stackup:
  drawing of 191 lines, arcs and shapes, not listed
  text "Layer" at 9790.34,7830 h60
  text "Name" at 10200.26,7830 h60
  text "Material" at 11130,7830 h60
  text "Thickness" at 11989.77,7830 h60
  text "Constant" at 12639.6,7830 h60
  text "Board Layer Stack" at 13209.46,7830 h60
  text "1" at 9790.34,7710 h60
  text "Top Overlay" at 10200.26,7710 h60
  text "2" at 9790.34,7590 h60
  text "Top Solder" at 10200.26,7590 h60
  text "Solder Resist" at 11130,7590 h60
  text "0.40mil" at 11989.77,7590 h60
  text "3.5" at 12639.6,7590 h60
  text "3" at 9790.34,7470 h60
  text "Top Layer" at 10200.26,7470 h60
  text "Copper" at 11130,7470 h60
  text "1.40mil" at 11989.77,7470 h60
  text "4" at 9790.34,7350 h60
  text "Dielectric1" at 10200.26,7350 h60
  text "FR-4" at 11130,7350 h60
  text "59.20mil" at 11989.77,7350 h60
  text "4.8" at 12639.6,7350 h60
  text "5" at 9790.34,7230 h60
  text "Bottom Layer" at 10200.26,7230 h60
  text "Copper" at 11130,7230 h60
  text "1.40mil" at 11989.77,7230 h60
  text "6" at 9790.34,7110 h60
  text "Bottom Solder" at 10200.26,7110 h60
  text "Solder Resist" at 11130,7110 h60
  text "0.40mil" at 11989.77,7110 h60
  text "3.5" at 12639.6,7110 h60
  text "7" at 9790.34,6990 h60
  text "Bottom Overlay" at 10200.26,6990 h60

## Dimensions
798.43,298.43 to 298.43,298.43 on M2 Board Dimensions
4300,4800 to 4300,0 on M2 Board Dimensions
0,0 to 4300,4800 on M2 Board Dimensions
0,-400 to 1000,-400 on M2 Board Dimensions
1180.32,180.32 to 1613.39,180.32 on M2 Board Dimensions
